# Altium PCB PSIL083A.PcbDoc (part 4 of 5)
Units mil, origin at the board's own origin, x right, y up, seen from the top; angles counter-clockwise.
Board outline 8750 x 2700 mil, 4 copper layers (Top Layer, Signal Layer 1, Signal Layer 2, Bottom Layer), stack 61.2 mil thick; 463 components, 395 nets, 2267 pads, 745 vias.
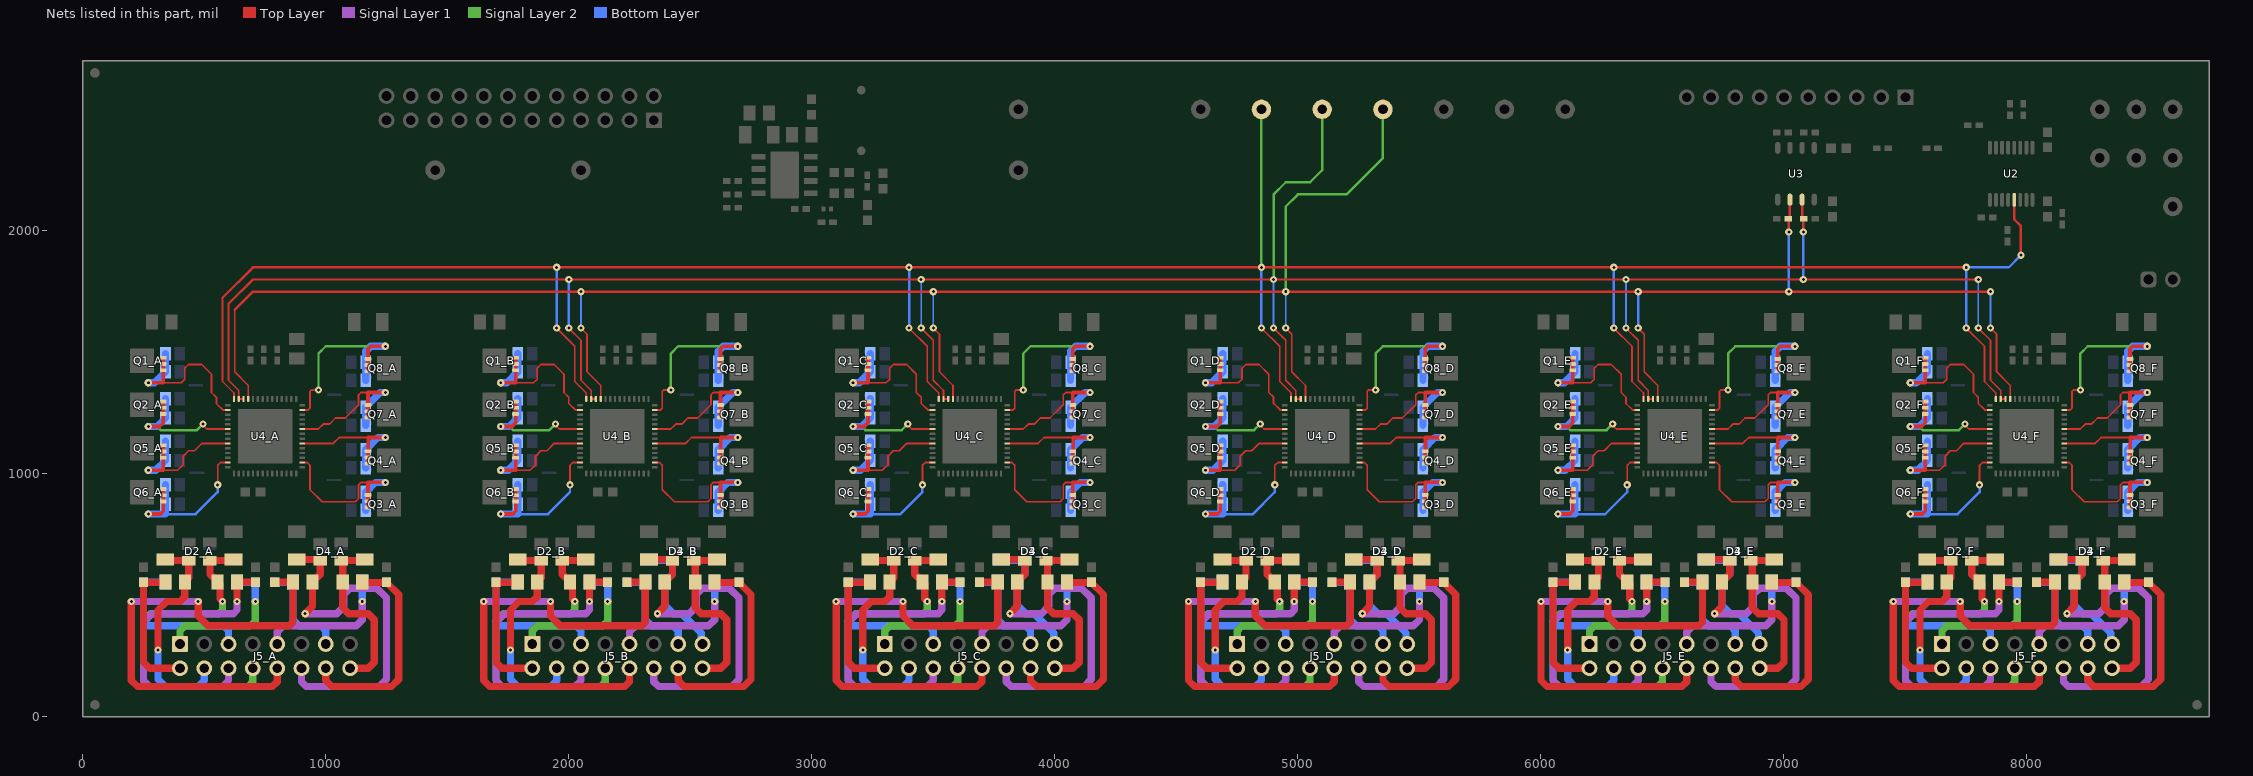
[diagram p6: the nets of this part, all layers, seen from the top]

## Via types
v1: diameter 30, hole 12, Top Layer to Bottom Layer, 610 vias
v2: diameter 19.68, hole 7.87, Top Layer to Bottom Layer, 130 vias
v3: diameter 19.68, hole 7.87, Top Layer to Bottom Layer, tented both sides, 4 vias
v4: diameter 34, hole 16, Top Layer to Bottom Layer, 1 vias

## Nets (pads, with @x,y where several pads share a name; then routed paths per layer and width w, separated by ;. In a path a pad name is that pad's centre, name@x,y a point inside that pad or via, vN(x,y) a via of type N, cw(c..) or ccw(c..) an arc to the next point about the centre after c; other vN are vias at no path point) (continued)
PSE_N4_B: C20_B.2 D3_B.3 F6_B.1 J5_B.15 | length 533.6
  Bottom Layer w30: F6_B.1@2334.41,643.5 D3_B.3@2426.69,643.5 2426.69,586.69 C20_B.2@2395,555 2395,460 2430,425 2465,425 2545,345 2545,305 J5_B.15@2550,300
PSE_N4_C: C20_C.2 D3_C.3 F6_C.1 J5_C.15 | length 533.6
  Bottom Layer w30: F6_C.1@3784.41,643.5 D3_C.3@3876.69,643.5 3876.69,586.69 C20_C.2@3845,555 3845,460 3880,425 3915,425 3995,345 3995,305 J5_C.15@4000,300
PSE_N4_D: C20_D.2 D3_D.3 F6_D.1 J5_D.15 | length 533.6
  Bottom Layer w30: F6_D.1@5234.41,643.5 D3_D.3@5326.69,643.5 5326.69,586.69 C20_D.2@5295,555 5295,460 5330,425 5365,425 5445,345 5445,305 J5_D.15@5450,300
PSE_N4_E: C20_E.2 D3_E.3 F6_E.1 J5_E.15 | length 533.6
  Bottom Layer w30: F6_E.1@6684.41,643.5 D3_E.3@6776.69,643.5 6776.69,586.69 C20_E.2@6745,555 6745,460 6780,425 6815,425 6895,345 6895,305 J5_E.15@6900,300
PSE_N4_F: C20_F.2 D3_F.3 F6_F.1 J5_F.15 | length 533.6
  Bottom Layer w30: F6_F.1@8134.41,643.5 D3_F.3@8226.69,643.5 8226.69,586.69 C20_F.2@8195,555 8195,460 8230,425 8265,425 8345,345 8345,305 J5_F.15@8350,300
PSE_N5_A: C17_A.2 D2_A.2 F3_A.1 J5_A.4 | length 928.3
  Top Layer w30: v1(310,275) 310,440 345,475 400,475 420,495 C17_A.2@420,555 436.69,571.69 D2_A.2@436.69,643.5 F3_A.1@344.41,643.5
  Bottom Layer w30: v1(310,275) 310,155 340,125 475,125 500,150 J5_A.4@500,200
PSE_N5_B: C17_B.2 D2_B.2 F3_B.1 J5_B.4 | length 928.3
  Top Layer w30: v1(1760,275) 1760,440 1795,475 1850,475 1870,495 C17_B.2@1870,555 1886.69,571.69 D2_B.2@1886.69,643.5 F3_B.1@1794.41,643.5
  Bottom Layer w30: v1(1760,275) 1760,155 1790,125 1925,125 1950,150 J5_B.4@1950,200
PSE_N5_C: C17_C.2 D2_C.2 F3_C.1 J5_C.4 | length 928.3
  Top Layer w30: v1(3210,275) 3210,440 3245,475 3300,475 3320,495 C17_C.2@3320,555 3336.69,571.69 D2_C.2@3336.69,643.5 F3_C.1@3244.41,643.5
  Bottom Layer w30: v1(3210,275) 3210,155 3240,125 3375,125 3400,150 J5_C.4@3400,200
PSE_N5_D: C17_D.2 D2_D.2 F3_D.1 J5_D.4 | length 928.3
  Top Layer w30: v1(4660,275) 4660,440 4695,475 4750,475 4770,495 C17_D.2@4770,555 4786.69,571.69 D2_D.2@4786.69,643.5 F3_D.1@4694.41,643.5
  Bottom Layer w30: v1(4660,275) 4660,155 4690,125 4825,125 4850,150 J5_D.4@4850,200
PSE_N5_E: C17_E.2 D2_E.2 F3_E.1 J5_E.4 | length 928.3
  Top Layer w30: v1(6110,275) 6110,440 6145,475 6200,475 6220,495 C17_E.2@6220,555 6236.69,571.69 D2_E.2@6236.69,643.5 F3_E.1@6144.41,643.5
  Bottom Layer w30: v1(6110,275) 6110,155 6140,125 6275,125 6300,150 J5_E.4@6300,200
PSE_N5_F: C17_F.2 D2_F.2 F3_F.1 J5_F.4 | length 928.3
  Top Layer w30: v1(7560,275) 7560,440 7595,475 7650,475 7670,495 C17_F.2@7670,555 7686.69,571.69 D2_F.2@7686.69,643.5 F3_F.1@7594.41,643.5
  Bottom Layer w30: v1(7560,275) 7560,155 7590,125 7725,125 7750,150 J5_F.4@7750,200
PSE_N6_A: C18_A.2 D2_A.3 F4_A.1 J5_A.8 | length 1429.5
  Top Layer w30: v1(575,475) 565,485 565,545 C18_A.2@555,555 523.31,586.69 D2_A.3@523.31,643.5 F4_A.1@615.59,643.5
  Signal Layer 2 w30: v1(575,475) 575,440 560,425 280,425 250,395 250,150 275,125 680,125 700,145 J5_A.8@700,200
PSE_N6_B: C18_B.2 D2_B.3 F4_B.1 J5_B.8 | length 1429.5
  Top Layer w30: v1(2025,475) 2015,485 2015,545 C18_B.2@2005,555 1973.31,586.69 D2_B.3@1973.31,643.5 F4_B.1@2065.59,643.5
  Signal Layer 2 w30: v1(2025,475) 2025,440 2010,425 1730,425 1700,395 1700,150 1725,125 2130,125 2150,145 J5_B.8@2150,200
PSE_N6_C: C18_C.2 D2_C.3 F4_C.1 J5_C.8 | length 1429.5
  Top Layer w30: v1(3475,475) 3465,485 3465,545 C18_C.2@3455,555 3423.31,586.69 D2_C.3@3423.31,643.5 F4_C.1@3515.59,643.5
  Signal Layer 2 w30: v1(3475,475) 3475,440 3460,425 3180,425 3150,395 3150,150 3175,125 3580,125 3600,145 J5_C.8@3600,200
PSE_N6_D: C18_D.2 D2_D.3 F4_D.1 J5_D.8 | length 1429.5
  Top Layer w30: v1(4925,475) 4915,485 4915,545 C18_D.2@4905,555 4873.31,586.69 D2_D.3@4873.31,643.5 F4_D.1@4965.59,643.5
  Signal Layer 2 w30: v1(4925,475) 4925,440 4910,425 4630,425 4600,395 4600,150 4625,125 5030,125 5050,145 J5_D.8@5050,200
PSE_N6_E: C18_E.2 D2_E.3 F4_E.1 J5_E.8 | length 1429.5
  Top Layer w30: v1(6375,475) 6365,485 6365,545 C18_E.2@6355,555 6323.31,586.69 D2_E.3@6323.31,643.5 F4_E.1@6415.59,643.5
  Signal Layer 2 w30: v1(6375,475) 6375,440 6360,425 6080,425 6050,395 6050,150 6075,125 6480,125 6500,145 J5_E.8@6500,200
PSE_N6_F: C18_F.2 D2_F.3 F4_F.1 J5_F.8 | length 1429.5
  Top Layer w30: v1(7825,475) 7815,485 7815,545 C18_F.2@7805,555 7773.31,586.69 D2_F.3@7773.31,643.5 F4_F.1@7865.59,643.5
  Signal Layer 2 w30: v1(7825,475) 7825,440 7810,425 7530,425 7500,395 7500,150 7525,125 7930,125 7950,145 J5_F.8@7950,200
PSE_N7_A: C21_A.2 D4_A.2 F7_A.1 J5_A.12 | length 1521.4
  Top Layer w30: F7_A.1@880,647.91 D4_A.2@972.28,647.91 ; v1(915,425) 945,455 C21_A.2@945,555 976.69,586.69 D4_A.2@976.69,643.5
  Signal Layer 1 w30: J5_A.12@900,200 900,145 920,125 1220,125 1250,155 1250,490 1210,530 1100,530 1075,505 1075,455 1045,425 v1(915,425)
PSE_N7_B: C21_B.2 D4_B.2 F7_B.1 J5_B.12 | length 1521.4
  Top Layer w30: F7_B.1@2330,647.91 D4_B.2@2422.28,647.91 ; v1(2365,425) 2395,455 C21_B.2@2395,555 2426.69,586.69 D4_B.2@2426.69,643.5
  Signal Layer 1 w30: J5_B.12@2350,200 2350,145 2370,125 2670,125 2700,155 2700,490 2660,530 2550,530 2525,505 2525,455 2495,425 v1(2365,425)
PSE_N7_C: C21_C.2 D4_C.2 F7_C.1 J5_C.12 | length 1521.4
  Top Layer w30: F7_C.1@3780,647.91 D4_C.2@3872.28,647.91 ; v1(3815,425) 3845,455 C21_C.2@3845,555 3876.69,586.69 D4_C.2@3876.69,643.5
  Signal Layer 1 w30: J5_C.12@3800,200 3800,145 3820,125 4120,125 4150,155 4150,490 4110,530 4000,530 3975,505 3975,455 3945,425 v1(3815,425)
PSE_N7_D: C21_D.2 D4_D.2 F7_D.1 J5_D.12 | length 1521.4
  Top Layer w30: F7_D.1@5230,647.91 D4_D.2@5322.28,647.91 ; v1(5265,425) 5295,455 C21_D.2@5295,555 5326.69,586.69 D4_D.2@5326.69,643.5
  Signal Layer 1 w30: J5_D.12@5250,200 5250,145 5270,125 5570,125 5600,155 5600,490 5560,530 5450,530 5425,505 5425,455 5395,425 v1(5265,425)
PSE_N7_E: C21_E.2 D4_E.2 F7_E.1 J5_E.12 | length 1521.4
  Top Layer w30: F7_E.1@6680,647.91 D4_E.2@6772.28,647.91 ; v1(6715,425) 6745,455 C21_E.2@6745,555 6776.69,586.69 D4_E.2@6776.69,643.5
  Signal Layer 1 w30: J5_E.12@6700,200 6700,145 6720,125 7020,125 7050,155 7050,490 7010,530 6900,530 6875,505 6875,455 6845,425 v1(6715,425)
PSE_N7_F: C21_F.2 D4_F.2 F7_F.1 J5_F.12 | length 1521.4
  Top Layer w30: F7_F.1@8130,647.91 D4_F.2@8222.28,647.91 ; v1(8165,425) 8195,455 C21_F.2@8195,555 8226.69,586.69 D4_F.2@8226.69,643.5
  Signal Layer 1 w30: J5_F.12@8150,200 8150,145 8170,125 8470,125 8500,155 8500,490 8460,530 8350,530 8325,505 8325,455 8295,425 v1(8165,425)
PSE_N8_A: C22_A.2 D4_A.3 F8_A.1 J5_A.16 | length 715.2
  Top Layer w30: D4_A.3@1063.31,643.5 F8_A.1@1155.59,643.5 ; D4_A.3@1070,636.81 C22_A.2@1070,555 1070,450 1095,425 1175,425 1200,400 1200,225 1175,200 J5_A.16@1100,200
PSE_N8_B: C22_B.2 D4_B.3 F8_B.1 J5_B.16 | length 715.2
  Top Layer w30: D4_B.3@2513.31,643.5 F8_B.1@2605.59,643.5 ; D4_B.3@2520,636.81 C22_B.2@2520,555 2520,450 2545,425 2625,425 2650,400 2650,225 2625,200 J5_B.16@2550,200
PSE_N8_C: C22_C.2 D4_C.3 F8_C.1 J5_C.16 | length 715.2
  Top Layer w30: D4_C.3@3963.31,643.5 F8_C.1@4055.59,643.5 ; D4_C.3@3970,636.81 C22_C.2@3970,555 3970,450 3995,425 4075,425 4100,400 4100,225 4075,200 J5_C.16@4000,200
PSE_N8_D: C22_D.2 D4_D.3 F8_D.1 J5_D.16 | length 715.2
  Top Layer w30: D4_D.3@5413.31,643.5 F8_D.1@5505.59,643.5 ; D4_D.3@5420,636.81 C22_D.2@5420,555 5420,450 5445,425 5525,425 5550,400 5550,225 5525,200 J5_D.16@5450,200
PSE_N8_E: C22_E.2 D4_E.3 F8_E.1 J5_E.16 | length 715.2
  Top Layer w30: D4_E.3@6863.31,643.5 F8_E.1@6955.59,643.5 ; D4_E.3@6870,636.81 C22_E.2@6870,555 6870,450 6895,425 6975,425 7000,400 7000,225 6975,200 J5_E.16@6900,200
PSE_N8_F: C22_F.2 D4_F.3 F8_F.1 J5_F.16 | length 715.2
  Top Layer w30: D4_F.3@8313.31,643.5 F8_F.1@8405.59,643.5 ; D4_F.3@8320,636.81 C22_F.2@8320,555 8320,450 8345,425 8425,425 8450,400 8450,225 8425,200 J5_F.16@8350,200
PSE_OSS_A: TP12.1 U2.13 U4_A.56 U4_B.56 U4_C.56 U4_D.56 U4_E.56 U4_F.56 | length 11757.6
  Top Layer w7: 575,1725 575,1380 622.05,1332.95 U4_A.56@622.05,1308.54 ; v1(1950,1600) 2025,1525 2025,1380 2072.05,1332.95 U4_B.56@2072.05,1308.54 ; v1(3400,1600) 3475,1525 3475,1380 3522.05,1332.95 U4_C.56@3522.05,1308.54 ; v1(4850,1600) 4925,1525 4925,1380 4972.05,1332.95 U4_D.56@4972.05,1308.54 ; v1(6300,1600) 6375,1525 6375,1380 6422.05,1332.95 U4_E.56@6422.05,1308.54 ; v1(7750,1600) 7825,1525 7825,1380 7872.05,1332.95 U4_F.56@7872.05,1308.54
  Top Layer w10: 575,1725 700,1850 v1(1950,1850) v1(3400,1850) v1(4850,1850) v1(6300,1850) v1(7750,1850) ; U2.13@7947.5,2127.72 7947.5,2047.5 7975,2020 v1(7975,1900)
  Signal Layer 2 w10: v1(4850,1850) TP12.1@4850,2500
  Bottom Layer w10: v1(1950,1600) v1(1950,1850) ; v1(3400,1600) v1(3400,1850) ; v1(4850,1600) v1(4850,1850) ; v1(6300,1600) v1(6300,1850) ; v1(7750,1600) v1(7750,1850) 7925,1850 v1(7975,1900)
PSE_P1_A: C15_A.1 J5_A.1 L2_A.2 | length 613.6
  Signal Layer 2 w30: J5_A.1@400,300 400,355 420,375 690,375 710,395 v1(710,475)
  Bottom Layer w30: C15_A.1@636.5,553.5 L2_A.2@710,553.5 v1(710,475)
PSE_P1_B: C15_B.1 J5_B.1 L2_B.2 | length 613.6
  Signal Layer 2 w30: J5_B.1@1850,300 1850,355 1870,375 2140,375 2160,395 v1(2160,475)
  Bottom Layer w30: C15_B.1@2086.5,553.5 L2_B.2@2160,553.5 v1(2160,475)
PSE_P1_C: C15_C.1 J5_C.1 L2_C.2 | length 613.6
  Signal Layer 2 w30: J5_C.1@3300,300 3300,355 3320,375 3590,375 3610,395 v1(3610,475)
  Bottom Layer w30: C15_C.1@3536.5,553.5 L2_C.2@3610,553.5 v1(3610,475)
PSE_P1_D: C15_D.1 J5_D.1 L2_D.2 | length 613.6
  Signal Layer 2 w30: J5_D.1@4750,300 4750,355 4770,375 5040,375 5060,395 v1(5060,475)
  Bottom Layer w30: C15_D.1@4986.5,553.5 L2_D.2@5060,553.5 v1(5060,475)
PSE_P1_E: C15_E.1 J5_E.1 L2_E.2 | length 613.6
  Signal Layer 2 w30: J5_E.1@6200,300 6200,355 6220,375 6490,375 6510,395 v1(6510,475)
  Bottom Layer w30: C15_E.1@6436.5,553.5 L2_E.2@6510,553.5 v1(6510,475)
PSE_P1_F: C15_F.1 J5_F.1 L2_F.2 | length 613.6
  Signal Layer 2 w30: J5_F.1@7650,300 7650,355 7670,375 7940,375 7960,395 v1(7960,475)
  Bottom Layer w30: C15_F.1@7886.5,553.5 L2_F.2@7960,553.5 v1(7960,475)
PSE_P2_A: C16_A.1 J5_A.5 L3_A.2 | length 665.6
  Bottom Layer w30: L3_A.2@250,553.5 250,395 270,375 580,375 600,355 J5_A.5@600,300 ; L3_A.2@254.43,555 C16_A.1@340,555
PSE_P2_B: C16_B.1 J5_B.5 L3_B.2 | length 665.6
  Bottom Layer w30: L3_B.2@1700,553.5 1700,395 1720,375 2030,375 2050,355 J5_B.5@2050,300 ; L3_B.2@1704.43,555 C16_B.1@1790,555
PSE_P2_C: C16_C.1 J5_C.5 L3_C.2 | length 665.6
  Bottom Layer w30: L3_C.2@3150,553.5 3150,395 3170,375 3480,375 3500,355 J5_C.5@3500,300 ; L3_C.2@3154.43,555 C16_C.1@3240,555
PSE_P2_D: C16_D.1 J5_D.5 L3_D.2 | length 665.6
  Bottom Layer w30: L3_D.2@4600,553.5 4600,395 4620,375 4930,375 4950,355 J5_D.5@4950,300 ; L3_D.2@4604.43,555 C16_D.1@4690,555
PSE_P2_E: C16_E.1 J5_E.5 L3_E.2 | length 665.6
  Bottom Layer w30: L3_E.2@6050,553.5 6050,395 6070,375 6380,375 6400,355 J5_E.5@6400,300 ; L3_E.2@6054.43,555 C16_E.1@6140,555
PSE_P2_F: C16_F.1 J5_F.5 L3_F.2 | length 665.6
  Bottom Layer w30: L3_F.2@7500,553.5 7500,395 7520,375 7830,375 7850,355 J5_F.5@7850,300 ; L3_F.2@7504.43,555 C16_F.1@7590,555
PSE_P3_A: C19_A.1 J5_A.9 L6_A.2 | length 671.2
  Signal Layer 1 w30: J5_A.9@800,300 800,350 825,375 1125,375 1150,400 v1(1150,475)
  Bottom Layer w30: v1(1150,475) C19_A.1@1150,552.01 ; C19_A.1@1151.5,553.5 L6_A.2@1250,553.5
PSE_P3_B: C19_B.1 J5_B.9 L6_B.2 | length 671.2
  Signal Layer 1 w30: J5_B.9@2250,300 2250,350 2275,375 2575,375 2600,400 v1(2600,475)
  Bottom Layer w30: v1(2600,475) C19_B.1@2600,552.01 ; C19_B.1@2601.5,553.5 L6_B.2@2700,553.5
PSE_P3_C: C19_C.1 J5_C.9 L6_C.2 | length 671.2
  Signal Layer 1 w30: J5_C.9@3700,300 3700,350 3725,375 4025,375 4050,400 v1(4050,475)
  Bottom Layer w30: v1(4050,475) C19_C.1@4050,552.01 ; C19_C.1@4051.5,553.5 L6_C.2@4150,553.5
PSE_P3_D: C19_D.1 J5_D.9 L6_D.2 | length 671.2
  Signal Layer 1 w30: J5_D.9@5150,300 5150,350 5175,375 5475,375 5500,400 v1(5500,475)
  Bottom Layer w30: v1(5500,475) C19_D.1@5500,552.01 ; C19_D.1@5501.5,553.5 L6_D.2@5600,553.5
PSE_P3_E: C19_E.1 J5_E.9 L6_E.2 | length 671.2
  Signal Layer 1 w30: J5_E.9@6600,300 6600,350 6625,375 6925,375 6950,400 v1(6950,475)
  Bottom Layer w30: v1(6950,475) C19_E.1@6950,552.01 ; C19_E.1@6951.5,553.5 L6_E.2@7050,553.5
PSE_P3_F: C19_F.1 J5_F.9 L6_F.2 | length 671.2
  Signal Layer 1 w30: J5_F.9@8050,300 8050,350 8075,375 8375,375 8400,400 v1(8400,475)
  Bottom Layer w30: v1(8400,475) C19_F.1@8400,552.01 ; C19_F.1@8401.5,553.5 L6_F.2@8500,553.5
PSE_P4_A: C20_A.1 J5_A.13 L7_A.2 | length 437.1
  Bottom Layer w30: L7_A.2@790,553.5 C20_A.1@863.5,553.5 ; C20_A.1@865,555 865,400 890,375 980,375 1000,355 J5_A.13@1000,300
PSE_P4_B: C20_B.1 J5_B.13 L7_B.2 | length 437.1
  Bottom Layer w30: L7_B.2@2240,553.5 C20_B.1@2313.5,553.5 ; C20_B.1@2315,555 2315,400 2340,375 2430,375 2450,355 J5_B.13@2450,300
PSE_P4_C: C20_C.1 J5_C.13 L7_C.2 | length 437.1
  Bottom Layer w30: L7_C.2@3690,553.5 C20_C.1@3763.5,553.5 ; C20_C.1@3765,555 3765,400 3790,375 3880,375 3900,355 J5_C.13@3900,300
PSE_P4_D: C20_D.1 J5_D.13 L7_D.2 | length 437.1
  Bottom Layer w30: L7_D.2@5140,553.5 C20_D.1@5213.5,553.5 ; C20_D.1@5215,555 5215,400 5240,375 5330,375 5350,355 J5_D.13@5350,300
PSE_P4_E: C20_E.1 J5_E.13 L7_E.2 | length 437.1
  Bottom Layer w30: L7_E.2@6590,553.5 C20_E.1@6663.5,553.5 ; C20_E.1@6665,555 6665,400 6690,375 6780,375 6800,355 J5_E.13@6800,300
PSE_P4_F: C20_F.1 J5_F.13 L7_F.2 | length 437.1
  Bottom Layer w30: L7_F.2@8040,553.5 C20_F.1@8113.5,553.5 ; C20_F.1@8115,555 8115,400 8140,375 8230,375 8250,355 J5_F.13@8250,300
PSE_P5_A: C17_A.1 J5_A.2 L4_A.2 | length 577.4
  Top Layer w30: C17_A.1@338.5,553.5 L4_A.2@250,553.5 250,225 275,200 J5_A.2@400,200
PSE_P5_B: C17_B.1 J5_B.2 L4_B.2 | length 577.4
  Top Layer w30: C17_B.1@1788.5,553.5 L4_B.2@1700,553.5 1700,225 1725,200 J5_B.2@1850,200
PSE_P5_C: C17_C.1 J5_C.2 L4_C.2 | length 577.4
  Top Layer w30: C17_C.1@3238.5,553.5 L4_C.2@3150,553.5 3150,225 3175,200 J5_C.2@3300,200
PSE_P5_D: C17_D.1 J5_D.2 L4_D.2 | length 577.4
  Top Layer w30: C17_D.1@4688.5,553.5 L4_D.2@4600,553.5 4600,225 4625,200 J5_D.2@4750,200
PSE_P5_E: C17_E.1 J5_E.2 L4_E.2 | length 577.4
  Top Layer w30: C17_E.1@6138.5,553.5 L4_E.2@6050,553.5 6050,225 6075,200 J5_E.2@6200,200
PSE_P5_F: C17_F.1 J5_F.2 L4_F.2 | length 577.4
  Top Layer w30: C17_F.1@7588.5,553.5 L4_F.2@7500,553.5 7500,225 7525,200 J5_F.2@7650,200
PSE_P6_A: C18_A.1 J5_A.6 L5_A.2 | length 1254.9
  Top Layer w30: v1(635,475) C18_A.1@635,555 L5_A.2@708.5,555
  Signal Layer 1 w30: J5_A.6@600,200 600,150 575,125 275,125 250,150 250,390 285,425 620,425 635,440 v1(635,475)
PSE_P6_B: C18_B.1 J5_B.6 L5_B.2 | length 1254.9
  Top Layer w30: v1(2085,475) C18_B.1@2085,555 L5_B.2@2158.5,555
  Signal Layer 1 w30: J5_B.6@2050,200 2050,150 2025,125 1725,125 1700,150 1700,390 1735,425 2070,425 2085,440 v1(2085,475)
PSE_P6_C: C18_C.1 J5_C.6 L5_C.2 | length 1254.9
  Top Layer w30: v1(3535,475) C18_C.1@3535,555 L5_C.2@3608.5,555
  Signal Layer 1 w30: J5_C.6@3500,200 3500,150 3475,125 3175,125 3150,150 3150,390 3185,425 3520,425 3535,440 v1(3535,475)
PSE_P6_D: C18_D.1 J5_D.6 L5_D.2 | length 1254.9
  Top Layer w30: v1(4985,475) C18_D.1@4985,555 L5_D.2@5058.5,555
  Signal Layer 1 w30: J5_D.6@4950,200 4950,150 4925,125 4625,125 4600,150 4600,390 4635,425 4970,425 4985,440 v1(4985,475)
PSE_P6_E: C18_E.1 J5_E.6 L5_E.2 | length 1254.9
  Top Layer w30: v1(6435,475) C18_E.1@6435,555 L5_E.2@6508.5,555
  Signal Layer 1 w30: J5_E.6@6400,200 6400,150 6375,125 6075,125 6050,150 6050,390 6085,425 6420,425 6435,440 v1(6435,475)
PSE_P6_F: C18_F.1 J5_F.6 L5_F.2 | length 1254.9
  Top Layer w30: v1(7885,475) C18_F.1@7885,555 L5_F.2@7958.5,555
  Signal Layer 1 w30: J5_F.6@7850,200 7850,150 7825,125 7525,125 7500,150 7500,390 7535,425 7870,425 7885,440 v1(7885,475)
PSE_P7_A: C21_A.1 J5_A.10 L8_A.2 | length 1984.9
  Top Layer w30: v1(200,475) 200,150 225,125 780,125 800,145 J5_A.10@800,200 ; v1(475,475) 475,415 515,375 850,375 865,390 C21_A.1@865,555 L8_A.2@791.5,555
  Signal Layer 1 w30: v1(200,475) v1(475,475)
PSE_P7_B: C21_B.1 J5_B.10 L8_B.2 | length 1984.9
  Top Layer w30: v1(1650,475) 1650,150 1675,125 2230,125 2250,145 J5_B.10@2250,200 ; v1(1925,475) 1925,415 1965,375 2300,375 2315,390 C21_B.1@2315,555 L8_B.2@2241.5,555
  Signal Layer 1 w30: v1(1650,475) v1(1925,475)
PSE_P7_C: C21_C.1 J5_C.10 L8_C.2 | length 1984.9
  Top Layer w30: v1(3100,475) 3100,150 3125,125 3680,125 3700,145 J5_C.10@3700,200 ; v1(3375,475) 3375,415 3415,375 3750,375 3765,390 C21_C.1@3765,555 L8_C.2@3691.5,555
  Signal Layer 1 w30: v1(3100,475) v1(3375,475)
PSE_P7_D: C21_D.1 J5_D.10 L8_D.2 | length 1984.9
  Top Layer w30: v1(4550,475) 4550,150 4575,125 5130,125 5150,145 J5_D.10@5150,200 ; v1(4825,475) 4825,415 4865,375 5200,375 5215,390 C21_D.1@5215,555 L8_D.2@5141.5,555
  Signal Layer 1 w30: v1(4550,475) v1(4825,475)
PSE_P7_E: C21_E.1 J5_E.10 L8_E.2 | length 1984.9
  Top Layer w30: v1(6000,475) 6000,150 6025,125 6580,125 6600,145 J5_E.10@6600,200 ; v1(6275,475) 6275,415 6315,375 6650,375 6665,390 C21_E.1@6665,555 L8_E.2@6591.5,555
  Signal Layer 1 w30: v1(6000,475) v1(6275,475)
PSE_P7_F: C21_F.1 J5_F.10 L8_F.2 | length 1984.9
  Top Layer w30: v1(7450,475) 7450,150 7475,125 8030,125 8050,145 J5_F.10@8050,200 ; v1(7725,475) 7725,415 7765,375 8100,375 8115,390 C21_F.1@8115,555 L8_F.2@8041.5,555
  Signal Layer 1 w30: v1(7450,475) v1(7725,475)
PSE_P8_A: C22_A.1 J5_A.14 L9_A.2 | length 890.5
  Top Layer w30: J5_A.14@1000,200 1000,150 1025,125 1270,125 1300,155 1300,503.5 L9_A.2@1250,553.5 C22_A.1@1151.5,553.5
PSE_P8_B: C22_B.1 J5_B.14 L9_B.2 | length 890.5
  Top Layer w30: J5_B.14@2450,200 2450,150 2475,125 2720,125 2750,155 2750,503.5 L9_B.2@2700,553.5 C22_B.1@2601.5,553.5
PSE_P8_C: C22_C.1 J5_C.14 L9_C.2 | length 890.5
  Top Layer w30: J5_C.14@3900,200 3900,150 3925,125 4170,125 4200,155 4200,503.5 L9_C.2@4150,553.5 C22_C.1@4051.5,553.5
PSE_P8_D: C22_D.1 J5_D.14 L9_D.2 | length 890.5
  Top Layer w30: J5_D.14@5350,200 5350,150 5375,125 5620,125 5650,155 5650,503.5 L9_D.2@5600,553.5 C22_D.1@5501.5,553.5
PSE_P8_E: C22_E.1 J5_E.14 L9_E.2 | length 890.5
  Top Layer w30: J5_E.14@6800,200 6800,150 6825,125 7070,125 7100,155 7100,503.5 L9_E.2@7050,553.5 C22_E.1@6951.5,553.5
PSE_P8_F: C22_F.1 J5_F.14 L9_F.2 | length 890.5
  Top Layer w30: J5_F.14@8250,200 8250,150 8275,125 8520,125 8550,155 8550,503.5 L9_F.2@8500,553.5 C22_F.1@8401.5,553.5
PSE_S1_A: Q1_A.1 Q1_A.2 Q1_A.3 R15_A.1 R16_A.1 U4_A.2 | length 787.1
  Top Layer w7: 330,1375 405,1375 420,1390 420,1435 435,1450 490,1450 530,1410 530,1335 550,1315 550,1290 576.73,1263.27 U4_A.2@596.46,1263.27
  Top Layer w15: v1(270,1375) 330,1375 331.02,1376.02 Q1_A.1@331.02,1426.61 Q1_A.2@331.02,1452.21 Q1_A.3@331.02,1477.8
  Bottom Layer w30: v1(270,1375) 295.47,1375 R16_A.1@340.47,1420 R15_A.1@340.47,1495
PSE_S1_B: Q1_B.1 Q1_B.2 Q1_B.3 R15_B.1 R16_B.1 U4_B.2 | length 787.1
  Top Layer w7: 1780,1375 1855,1375 1870,1390 1870,1435 1885,1450 1940,1450 1980,1410 1980,1335 2000,1315 2000,1290 2026.73,1263.27 U4_B.2@2046.46,1263.27
  Top Layer w15: v1(1720,1375) 1780,1375 1781.02,1376.02 Q1_B.1@1781.02,1426.61 Q1_B.2@1781.02,1452.21 Q1_B.3@1781.02,1477.8
  Bottom Layer w30: v1(1720,1375) 1745.47,1375 R16_B.1@1790.47,1420 R15_B.1@1790.47,1495
PSE_S1_C: Q1_C.1 Q1_C.2 Q1_C.3 R15_C.1 R16_C.1 U4_C.2 | length 787.1
  Top Layer w7: 3230,1375 3305,1375 3320,1390 3320,1435 3335,1450 3390,1450 3430,1410 3430,1335 3450,1315 3450,1290 3476.73,1263.27 U4_C.2@3496.46,1263.27
  Top Layer w15: v1(3170,1375) 3230,1375 3231.02,1376.02 Q1_C.1@3231.02,1426.61 Q1_C.2@3231.02,1452.21 Q1_C.3@3231.02,1477.8
  Bottom Layer w30: v1(3170,1375) 3195.47,1375 R16_C.1@3240.47,1420 R15_C.1@3240.47,1495
PSE_S1_D: Q1_D.1 Q1_D.2 Q1_D.3 R15_D.1 R16_D.1 U4_D.2 | length 787.1
  Top Layer w7: 4680,1375 4755,1375 4770,1390 4770,1435 4785,1450 4840,1450 4880,1410 4880,1335 4900,1315 4900,1290 4926.73,1263.27 U4_D.2@4946.46,1263.27
  Top Layer w15: v1(4620,1375) 4680,1375 4681.02,1376.02 Q1_D.1@4681.02,1426.61 Q1_D.2@4681.02,1452.21 Q1_D.3@4681.02,1477.8
  Bottom Layer w30: v1(4620,1375) 4645.47,1375 R16_D.1@4690.47,1420 R15_D.1@4690.47,1495
PSE_S1_E: Q1_E.1 Q1_E.2 Q1_E.3 R15_E.1 R16_E.1 U4_E.2 | length 787.1
  Top Layer w7: 6130,1375 6205,1375 6220,1390 6220,1435 6235,1450 6290,1450 6330,1410 6330,1335 6350,1315 6350,1290 6376.73,1263.27 U4_E.2@6396.46,1263.27
  Top Layer w15: v1(6070,1375) 6130,1375 6131.02,1376.02 Q1_E.1@6131.02,1426.61 Q1_E.2@6131.02,1452.21 Q1_E.3@6131.02,1477.8
  Bottom Layer w30: v1(6070,1375) 6095.47,1375 R16_E.1@6140.47,1420 R15_E.1@6140.47,1495
PSE_S1_F: Q1_F.1 Q1_F.2 Q1_F.3 R15_F.1 R16_F.1 U4_F.2 | length 787.1
  Top Layer w7: 7580,1375 7655,1375 7670,1390 7670,1435 7685,1450 7740,1450 7780,1410 7780,1335 7800,1315 7800,1290 7826.73,1263.27 U4_F.2@7846.46,1263.27
  Top Layer w15: v1(7520,1375) 7580,1375 7581.02,1376.02 Q1_F.1@7581.02,1426.61 Q1_F.2@7581.02,1452.21 Q1_F.3@7581.02,1477.8
  Bottom Layer w30: v1(7520,1375) 7545.47,1375 R16_F.1@7590.47,1420 R15_F.1@7590.47,1495
PSE_S2_A: Q2_A.1 Q2_A.2 Q2_A.3 R17_A.1 R18_A.1 U4_A.6 | length 675.9
  Top Layer w7: v1@490,1205 510.47,1184.53 U4_A.6@596.46,1184.53
  Top Layer w15: v1(270,1195) 315,1195 331.02,1211.02 Q2_A.1@331.02,1246.61 Q2_A.2@331.02,1272.21 Q2_A.3@331.02,1297.8
  Signal Layer 2 w10: v1(270,1195) 305.47,1195 320.47,1180 470,1180 v1(495,1205)
  Bottom Layer w30: v1(270,1195) 305.47,1195 R18_A.1@340.47,1230 R17_A.1@340.47,1310
PSE_S2_B: Q2_B.1 Q2_B.2 Q2_B.3 R17_B.1 R18_B.1 U4_B.6 | length 675.9
  Top Layer w7: v1@1940,1205 1960.47,1184.53 U4_B.6@2046.46,1184.53
  Top Layer w15: v1(1720,1195) 1765,1195 1781.02,1211.02 Q2_B.1@1781.02,1246.61 Q2_B.2@1781.02,1272.21 Q2_B.3@1781.02,1297.8
  Signal Layer 2 w10: v1(1720,1195) 1755.47,1195 1770.47,1180 1920,1180 v1(1945,1205)
  Bottom Layer w30: v1(1720,1195) 1755.47,1195 R18_B.1@1790.47,1230 R17_B.1@1790.47,1310
PSE_S2_C: Q2_C.1 Q2_C.2 Q2_C.3 R17_C.1 R18_C.1 U4_C.6 | length 675.9
  Top Layer w7: v1@3390,1205 3410.47,1184.53 U4_C.6@3496.46,1184.53
  Top Layer w15: v1(3170,1195) 3215,1195 3231.02,1211.02 Q2_C.1@3231.02,1246.61 Q2_C.2@3231.02,1272.21 Q2_C.3@3231.02,1297.8
  Signal Layer 2 w10: v1(3170,1195) 3205.47,1195 3220.47,1180 3370,1180 v1(3395,1205)
  Bottom Layer w30: v1(3170,1195) 3205.47,1195 R18_C.1@3240.47,1230 R17_C.1@3240.47,1310
PSE_S2_D: Q2_D.1 Q2_D.2 Q2_D.3 R17_D.1 R18_D.1 U4_D.6 | length 675.9
  Top Layer w7: v1@4840,1205 4860.47,1184.53 U4_D.6@4946.46,1184.53
  Top Layer w15: v1(4620,1195) 4665,1195 4681.02,1211.02 Q2_D.1@4681.02,1246.61 Q2_D.2@4681.02,1272.21 Q2_D.3@4681.02,1297.8
  Signal Layer 2 w10: v1(4620,1195) 4655.47,1195 4670.47,1180 4820,1180 v1(4845,1205)
  Bottom Layer w30: v1(4620,1195) 4655.47,1195 R18_D.1@4690.47,1230 R17_D.1@4690.47,1310
PSE_S2_E: Q2_E.1 Q2_E.2 Q2_E.3 R17_E.1 R18_E.1 U4_E.6 | length 675.9
  Top Layer w7: v1@6290,1205 6310.47,1184.53 U4_E.6@6396.46,1184.53
  Top Layer w15: v1(6070,1195) 6115,1195 6131.02,1211.02 Q2_E.1@6131.02,1246.61 Q2_E.2@6131.02,1272.21 Q2_E.3@6131.02,1297.8
  Signal Layer 2 w10: v1(6070,1195) 6105.47,1195 6120.47,1180 6270,1180 v1(6295,1205)
  Bottom Layer w30: v1(6070,1195) 6105.47,1195 R18_E.1@6140.47,1230 R17_E.1@6140.47,1310
PSE_S2_F: Q2_F.1 Q2_F.2 Q2_F.3 R17_F.1 R18_F.1 U4_F.6 | length 675.9
  Top Layer w7: v1@7740,1205 7760.47,1184.53 U4_F.6@7846.46,1184.53
  Top Layer w15: v1(7520,1195) 7565,1195 7581.02,1211.02 Q2_F.1@7581.02,1246.61 Q2_F.2@7581.02,1272.21 Q2_F.3@7581.02,1297.8
  Signal Layer 2 w10: v1(7520,1195) 7555.47,1195 7570.47,1180 7720,1180 v1(7745,1205)
  Bottom Layer w30: v1(7520,1195) 7555.47,1195 R18_F.1@7590.47,1230 R17_F.1@7590.47,1310
PSE_S3_A: Q5_A.1 Q5_A.2 Q5_A.3 R23_A.1 R24_A.1 U4_A.9 | length 662.6
  Top Layer w7: 331.02,1015 390,1015 413.31,1038.31 413.31,1073.31 435,1095 460,1095 490.47,1125.47 U4_A.9@596.46,1125.47
  Top Layer w15: v1(270,1015) 331.02,1015 Q5_A.1@331.02,1066.61 Q5_A.2@331.02,1092.21 Q5_A.3@331.02,1117.8
  Bottom Layer w30: v1(270,1015) 300.47,1015 R24_A.1@340.47,1055 R23_A.1@340.47,1135
PSE_S3_B: Q5_B.1 Q5_B.2 Q5_B.3 R23_B.1 R24_B.1 U4_B.9 | length 662.6
  Top Layer w7: 1781.02,1015 1840,1015 1863.31,1038.31 1863.31,1073.31 1885,1095 1910,1095 1940.47,1125.47 U4_B.9@2046.46,1125.47
  Top Layer w15: v1(1720,1015) 1781.02,1015 Q5_B.1@1781.02,1066.61 Q5_B.2@1781.02,1092.21 Q5_B.3@1781.02,1117.8
  Bottom Layer w30: v1(1720,1015) 1750.47,1015 R24_B.1@1790.47,1055 R23_B.1@1790.47,1135
PSE_S3_C: Q5_C.1 Q5_C.2 Q5_C.3 R23_C.1 R24_C.1 U4_C.9 | length 662.6
  Top Layer w7: 3231.02,1015 3290,1015 3313.31,1038.31 3313.31,1073.31 3335,1095 3360,1095 3390.47,1125.47 U4_C.9@3496.46,1125.47
  Top Layer w15: v1(3170,1015) 3231.02,1015 Q5_C.1@3231.02,1066.61 Q5_C.2@3231.02,1092.21 Q5_C.3@3231.02,1117.8
  Bottom Layer w30: v1(3170,1015) 3200.47,1015 R24_C.1@3240.47,1055 R23_C.1@3240.47,1135
PSE_S3_D: Q5_D.1 Q5_D.2 Q5_D.3 R23_D.1 R24_D.1 U4_D.9 | length 662.6
  Top Layer w7: 4681.02,1015 4740,1015 4763.31,1038.31 4763.31,1073.31 4785,1095 4810,1095 4840.47,1125.47 U4_D.9@4946.46,1125.47
  Top Layer w15: v1(4620,1015) 4681.02,1015 Q5_D.1@4681.02,1066.61 Q5_D.2@4681.02,1092.21 Q5_D.3@4681.02,1117.8
  Bottom Layer w30: v1(4620,1015) 4650.47,1015 R24_D.1@4690.47,1055 R23_D.1@4690.47,1135
PSE_S3_E: Q5_E.1 Q5_E.2 Q5_E.3 R23_E.1 R24_E.1 U4_E.9 | length 662.6
  Top Layer w7: 6131.02,1015 6190,1015 6213.31,1038.31 6213.31,1073.31 6235,1095 6260,1095 6290.47,1125.47 U4_E.9@6396.46,1125.47
  Top Layer w15: v1(6070,1015) 6131.02,1015 Q5_E.1@6131.02,1066.61 Q5_E.2@6131.02,1092.21 Q5_E.3@6131.02,1117.8
  Bottom Layer w30: v1(6070,1015) 6100.47,1015 R24_E.1@6140.47,1055 R23_E.1@6140.47,1135
PSE_S3_F: Q5_F.1 Q5_F.2 Q5_F.3 R23_F.1 R24_F.1 U4_F.9 | length 662.6
  Top Layer w7: 7581.02,1015 7640,1015 7663.31,1038.31 7663.31,1073.31 7685,1095 7710,1095 7740.47,1125.47 U4_F.9@7846.46,1125.47
  Top Layer w15: v1(7520,1015) 7581.02,1015 Q5_F.1@7581.02,1066.61 Q5_F.2@7581.02,1092.21 Q5_F.3@7581.02,1117.8
  Bottom Layer w30: v1(7520,1015) 7550.47,1015 R24_F.1@7590.47,1055 R23_F.1@7590.47,1135
PSE_S4_A: Q6_A.1 Q6_A.2 Q6_A.3 R25_A.1 R26_A.1 U4_A.13 | length 755.7
  Top Layer w7: v1(555,955) 555,1035 566.73,1046.73 U4_A.13@596.46,1046.73
  Top Layer w15: v1(270,835) 320,835 331.02,846.02 Q6_A.1@331.02,886.61 Q6_A.2@331.02,912.21 Q6_A.3@331.02,937.8
  Bottom Layer w10: 340.91,834.57 464.57,834.57 555,925 v1(555,955)
  Bottom Layer w30: v1(270,835) 340.47,835 R26_A.1@340.47,875 R25_A.1@340.47,955
PSE_S4_B: Q6_B.1 Q6_B.2 Q6_B.3 R25_B.1 R26_B.1 U4_B.13 | length 755.7
  Top Layer w7: v1(2005,955) 2005,1035 2016.73,1046.73 U4_B.13@2046.46,1046.73
  Top Layer w15: v1(1720,835) 1770,835 1781.02,846.02 Q6_B.1@1781.02,886.61 Q6_B.2@1781.02,912.21 Q6_B.3@1781.02,937.8
  Bottom Layer w10: 1790.91,834.57 1914.57,834.57 2005,925 v1(2005,955)
  Bottom Layer w30: v1(1720,835) 1790.47,835 R26_B.1@1790.47,875 R25_B.1@1790.47,955
PSE_S4_C: Q6_C.1 Q6_C.2 Q6_C.3 R25_C.1 R26_C.1 U4_C.13 | length 755.7
  Top Layer w7: v1(3455,955) 3455,1035 3466.73,1046.73 U4_C.13@3496.46,1046.73
  Top Layer w15: v1(3170,835) 3220,835 3231.02,846.02 Q6_C.1@3231.02,886.61 Q6_C.2@3231.02,912.21 Q6_C.3@3231.02,937.8
  Bottom Layer w10: 3240.91,834.57 3364.57,834.57 3455,925 v1(3455,955)
  Bottom Layer w30: v1(3170,835) 3240.47,835 R26_C.1@3240.47,875 R25_C.1@3240.47,955
PSE_S4_D: Q6_D.1 Q6_D.2 Q6_D.3 R25_D.1 R26_D.1 U4_D.13 | length 755.7
  Top Layer w7: v1(4905,955) 4905,1035 4916.73,1046.73 U4_D.13@4946.46,1046.73
  Top Layer w15: v1(4620,835) 4670,835 4681.02,846.02 Q6_D.1@4681.02,886.61 Q6_D.2@4681.02,912.21 Q6_D.3@4681.02,937.8
  Bottom Layer w10: 4690.91,834.57 4814.57,834.57 4905,925 v1(4905,955)
  Bottom Layer w30: v1(4620,835) 4690.47,835 R26_D.1@4690.47,875 R25_D.1@4690.47,955
PSE_S4_E: Q6_E.1 Q6_E.2 Q6_E.3 R25_E.1 R26_E.1 U4_E.13 | length 755.7
  Top Layer w7: v1(6355,955) 6355,1035 6366.73,1046.73 U4_E.13@6396.46,1046.73
  Top Layer w15: v1(6070,835) 6120,835 6131.02,846.02 Q6_E.1@6131.02,886.61 Q6_E.2@6131.02,912.21 Q6_E.3@6131.02,937.8
  Bottom Layer w10: 6140.91,834.57 6264.57,834.57 6355,925 v1(6355,955)
  Bottom Layer w30: v1(6070,835) 6140.47,835 R26_E.1@6140.47,875 R25_E.1@6140.47,955
PSE_S4_F: Q6_F.1 Q6_F.2 Q6_F.3 R25_F.1 R26_F.1 U4_F.13 | length 755.7
  Top Layer w7: v1(7805,955) 7805,1035 7816.73,1046.73 U4_F.13@7846.46,1046.73
  Top Layer w15: v1(7520,835) 7570,835 7581.02,846.02 Q6_F.1@7581.02,886.61 Q6_F.2@7581.02,912.21 Q6_F.3@7581.02,937.8
  Bottom Layer w10: 7590.91,834.57 7714.57,834.57 7805,925 v1(7805,955)
  Bottom Layer w30: v1(7520,835) 7590.47,835 R26_F.1@7590.47,875 R25_F.1@7590.47,955
PSE_S5_A: Q3_A.1 Q3_A.2 Q3_A.3 R19_A.1 R20_A.1 U4_A.30 | length 809.1
  Top Layer w7: U4_A.30@903.54,1046.73 923.27,1046.73 935,1035 935,935 985,885 1121.5,885 1135,898.5 1135,955 1145,965 1175,965
  Top Layer w15: Q3_A.3@1173.98,862.21 Q3_A.2@1173.98,887.8 Q3_A.1@1173.98,913.39 1173.98,965 v1(1245,965)
  Bottom Layer w30: R19_A.1@1164.53,850 R20_A.1@1164.53,925 1204.53,965 v1(1245,965)
PSE_S5_B: Q3_B.1 Q3_B.2 Q3_B.3 R19_B.1 R20_B.1 U4_B.30 | length 809.1
  Top Layer w7: U4_B.30@2353.54,1046.73 2373.27,1046.73 2385,1035 2385,935 2435,885 2571.5,885 2585,898.5 2585,955 2595,965 2625,965
  Top Layer w15: Q3_B.3@2623.98,862.21 Q3_B.2@2623.98,887.8 Q3_B.1@2623.98,913.39 2623.98,965 v1(2695,965)
  Bottom Layer w30: R19_B.1@2614.53,850 R20_B.1@2614.53,925 2654.53,965 v1(2695,965)
PSE_S5_C: Q3_C.1 Q3_C.2 Q3_C.3 R19_C.1 R20_C.1 U4_C.30 | length 809.1
  Top Layer w7: U4_C.30@3803.54,1046.73 3823.27,1046.73 3835,1035 3835,935 3885,885 4021.5,885 4035,898.5 4035,955 4045,965 4075,965
  Top Layer w15: Q3_C.3@4073.98,862.21 Q3_C.2@4073.98,887.8 Q3_C.1@4073.98,913.39 4073.98,965 v1(4145,965)
  Bottom Layer w30: R19_C.1@4064.53,850 R20_C.1@4064.53,925 4104.53,965 v1(4145,965)
PSE_S5_D: Q3_D.1 Q3_D.2 Q3_D.3 R19_D.1 R20_D.1 U4_D.30 | length 809.1
  Top Layer w7: U4_D.30@5253.54,1046.73 5273.27,1046.73 5285,1035 5285,935 5335,885 5471.5,885 5485,898.5 5485,955 5495,965 5525,965
  Top Layer w15: Q3_D.3@5523.98,862.21 Q3_D.2@5523.98,887.8 Q3_D.1@5523.98,913.39 5523.98,965 v1(5595,965)
  Bottom Layer w30: R19_D.1@5514.53,850 R20_D.1@5514.53,925 5554.53,965 v1(5595,965)
PSE_S5_E: Q3_E.1 Q3_E.2 Q3_E.3 R19_E.1 R20_E.1 U4_E.30 | length 809.1
  Top Layer w7: U4_E.30@6703.54,1046.73 6723.27,1046.73 6735,1035 6735,935 6785,885 6921.5,885 6935,898.5 6935,955 6945,965 6975,965
  Top Layer w15: Q3_E.3@6973.98,862.21 Q3_E.2@6973.98,887.8 Q3_E.1@6973.98,913.39 6973.98,965 v1(7045,965)
  Bottom Layer w30: R19_E.1@6964.53,850 R20_E.1@6964.53,925 7004.53,965 v1(7045,965)
PSE_S5_F: Q3_F.1 Q3_F.2 Q3_F.3 R19_F.1 R20_F.1 U4_F.30 | length 809.1
  Top Layer w7: U4_F.30@8153.54,1046.73 8173.27,1046.73 8185,1035 8185,935 8235,885 8371.5,885 8385,898.5 8385,955 8395,965 8425,965
  Top Layer w15: Q3_F.3@8423.98,862.21 Q3_F.2@8423.98,887.8 Q3_F.1@8423.98,913.39 8423.98,965 v1(8495,965)
  Bottom Layer w30: R19_F.1@8414.53,850 R20_F.1@8414.53,925 8454.53,965 v1(8495,965)
PSE_S6_A: Q4_A.1 Q4_A.2 Q4_A.3 R21_A.1 R22_A.1 U4_A.34 | length 634.6
  Top Layer w7: U4_A.34@903.54,1125.47 1030.47,1125.47 1055,1150 1175,1150
  Top Layer w15: Q4_A.3@1173.98,1042.21 Q4_A.2@1173.98,1067.8 Q4_A.1@1173.98,1093.39 ; Q4_A.1@1175,1094.41 1175,1150 v1(1245,1150)
  Bottom Layer w30: R21_A.1@1164.53,1025 R22_A.1@1164.53,1100 1214.53,1150 v1(1245,1150)
PSE_S6_B: Q4_B.1 Q4_B.2 Q4_B.3 R21_B.1 R22_B.1 U4_B.34 | length 634.6
  Top Layer w7: U4_B.34@2353.54,1125.47 2480.47,1125.47 2505,1150 2625,1150
  Top Layer w15: Q4_B.3@2623.98,1042.21 Q4_B.2@2623.98,1067.8 Q4_B.1@2623.98,1093.39 ; Q4_B.1@2625,1094.41 2625,1150 v1(2695,1150)
  Bottom Layer w30: R21_B.1@2614.53,1025 R22_B.1@2614.53,1100 2664.53,1150 v1(2695,1150)
PSE_S6_C: Q4_C.1 Q4_C.2 Q4_C.3 R21_C.1 R22_C.1 U4_C.34 | length 634.6
  Top Layer w7: U4_C.34@3803.54,1125.47 3930.47,1125.47 3955,1150 4075,1150
  Top Layer w15: Q4_C.3@4073.98,1042.21 Q4_C.2@4073.98,1067.8 Q4_C.1@4073.98,1093.39 ; Q4_C.1@4075,1094.41 4075,1150 v1(4145,1150)
  Bottom Layer w30: R21_C.1@4064.53,1025 R22_C.1@4064.53,1100 4114.53,1150 v1(4145,1150)
PSE_S6_D: Q4_D.1 Q4_D.2 Q4_D.3 R21_D.1 R22_D.1 U4_D.34 | length 634.6
  Top Layer w7: U4_D.34@5253.54,1125.47 5380.47,1125.47 5405,1150 5525,1150
  Top Layer w15: Q4_D.3@5523.98,1042.21 Q4_D.2@5523.98,1067.8 Q4_D.1@5523.98,1093.39 ; Q4_D.1@5525,1094.41 5525,1150 v1(5595,1150)
  Bottom Layer w30: R21_D.1@5514.53,1025 R22_D.1@5514.53,1100 5564.53,1150 v1(5595,1150)
PSE_S6_E: Q4_E.1 Q4_E.2 Q4_E.3 R21_E.1 R22_E.1 U4_E.34 | length 634.6
  Top Layer w7: U4_E.34@6703.54,1125.47 6830.47,1125.47 6855,1150 6975,1150
  Top Layer w15: Q4_E.3@6973.98,1042.21 Q4_E.2@6973.98,1067.8 Q4_E.1@6973.98,1093.39 ; Q4_E.1@6975,1094.41 6975,1150 v1(7045,1150)
  Bottom Layer w30: R21_E.1@6964.53,1025 R22_E.1@6964.53,1100 7014.53,1150 v1(7045,1150)
PSE_S6_F: Q4_F.1 Q4_F.2 Q4_F.3 R21_F.1 R22_F.1 U4_F.34 | length 634.6
  Top Layer w7: U4_F.34@8153.54,1125.47 8280.47,1125.47 8305,1150 8425,1150
  Top Layer w15: Q4_F.3@8423.98,1042.21 Q4_F.2@8423.98,1067.8 Q4_F.1@8423.98,1093.39 ; Q4_F.1@8425,1094.41 8425,1150 v1(8495,1150)
  Bottom Layer w30: R21_F.1@8414.53,1025 R22_F.1@8414.53,1100 8464.53,1150 v1(8495,1150)
PSE_S7_A: Q7_A.1 Q7_A.2 Q7_A.3 R27_A.1 R28_A.1 U4_A.37 | length 710.3
  Top Layer w7: U4_A.37@903.54,1184.53 969.53,1184.53 990,1205 1015,1205 1040,1230 1080,1230 1135,1285 1135,1325 1145,1335 1173.98,1335
  Top Layer w15: Q7_A.3@1173.98,1232.21 Q7_A.2@1173.98,1257.8 Q7_A.1@1173.98,1283.39 1173.98,1335 v1(1245,1335)
  Bottom Layer w30: R27_A.1@1164.53,1200 R28_A.1@1164.53,1275 1224.53,1335 v1(1245,1335)
PSE_S7_B: Q7_B.1 Q7_B.2 Q7_B.3 R27_B.1 R28_B.1 U4_B.37 | length 710.3
  Top Layer w7: U4_B.37@2353.54,1184.53 2419.53,1184.53 2440,1205 2465,1205 2490,1230 2530,1230 2585,1285 2585,1325 2595,1335 2623.98,1335
  Top Layer w15: Q7_B.3@2623.98,1232.21 Q7_B.2@2623.98,1257.8 Q7_B.1@2623.98,1283.39 2623.98,1335 v1(2695,1335)
  Bottom Layer w30: R27_B.1@2614.53,1200 R28_B.1@2614.53,1275 2674.53,1335 v1(2695,1335)
PSE_S7_C: Q7_C.1 Q7_C.2 Q7_C.3 R27_C.1 R28_C.1 U4_C.37 | length 710.3
  Top Layer w7: U4_C.37@3803.54,1184.53 3869.53,1184.53 3890,1205 3915,1205 3940,1230 3980,1230 4035,1285 4035,1325 4045,1335 4073.98,1335
  Top Layer w15: Q7_C.3@4073.98,1232.21 Q7_C.2@4073.98,1257.8 Q7_C.1@4073.98,1283.39 4073.98,1335 v1(4145,1335)
  Bottom Layer w30: R27_C.1@4064.53,1200 R28_C.1@4064.53,1275 4124.53,1335 v1(4145,1335)
PSE_S7_D: Q7_D.1 Q7_D.2 Q7_D.3 R27_D.1 R28_D.1 U4_D.37 | length 710.3
  Top Layer w7: U4_D.37@5253.54,1184.53 5319.53,1184.53 5340,1205 5365,1205 5390,1230 5430,1230 5485,1285 5485,1325 5495,1335 5523.98,1335
  Top Layer w15: Q7_D.3@5523.98,1232.21 Q7_D.2@5523.98,1257.8 Q7_D.1@5523.98,1283.39 5523.98,1335 v1(5595,1335)
  Bottom Layer w30: R27_D.1@5514.53,1200 R28_D.1@5514.53,1275 5574.53,1335 v1(5595,1335)
PSE_S7_E: Q7_E.1 Q7_E.2 Q7_E.3 R27_E.1 R28_E.1 U4_E.37 | length 710.3
  Top Layer w7: U4_E.37@6703.54,1184.53 6769.53,1184.53 6790,1205 6815,1205 6840,1230 6880,1230 6935,1285 6935,1325 6945,1335 6973.98,1335
  Top Layer w15: Q7_E.3@6973.98,1232.21 Q7_E.2@6973.98,1257.8 Q7_E.1@6973.98,1283.39 6973.98,1335 v1(7045,1335)
  Bottom Layer w30: R27_E.1@6964.53,1200 R28_E.1@6964.53,1275 7024.53,1335 v1(7045,1335)
PSE_S7_F: Q7_F.1 Q7_F.2 Q7_F.3 R27_F.1 R28_F.1 U4_F.37 | length 710.3
  Top Layer w7: U4_F.37@8153.54,1184.53 8219.53,1184.53 8240,1205 8265,1205 8290,1230 8330,1230 8385,1285 8385,1325 8395,1335 8423.98,1335
  Top Layer w15: Q7_F.3@8423.98,1232.21 Q7_F.2@8423.98,1257.8 Q7_F.1@8423.98,1283.39 8423.98,1335 v1(8495,1335)
  Bottom Layer w30: R27_F.1@8414.53,1200 R28_F.1@8414.53,1275 8474.53,1335 v1(8495,1335)
PSE_S8_A: Q8_A.1 Q8_A.2 Q8_A.3 R29_A.1 R30_A.1 U4_A.41 | length 954.6
  Top Layer w7: U4_A.41@903.54,1263.27 928.27,1263.27 935,1270 935,1340 940,1345 v1(970,1345)
  Top Layer w15: Q8_A.3@1173.98,1422.21 Q8_A.2@1173.98,1447.8 Q8_A.1@1173.98,1473.39 1173.98,1513.98 1185,1525 v1(1245,1525)
  Signal Layer 2 w10: v1(970,1345) 970,1495 1000,1525 v1(1245,1525)
  Bottom Layer w30: R29_A.1@1164.53,1385 R30_A.1@1164.53,1460 1164.53,1504.53 1185,1525 v1(1245,1525)
PSE_S8_B: Q8_B.1 Q8_B.2 Q8_B.3 R29_B.1 R30_B.1 U4_B.41 | length 954.6
  Top Layer w7: U4_B.41@2353.54,1263.27 2378.27,1263.27 2385,1270 2385,1340 2390,1345 v1(2420,1345)
  Top Layer w15: Q8_B.3@2623.98,1422.21 Q8_B.2@2623.98,1447.8 Q8_B.1@2623.98,1473.39 2623.98,1513.98 2635,1525 v1(2695,1525)
  Signal Layer 2 w10: v1(2420,1345) 2420,1495 2450,1525 v1(2695,1525)
  Bottom Layer w30: R29_B.1@2614.53,1385 R30_B.1@2614.53,1460 2614.53,1504.53 2635,1525 v1(2695,1525)
PSE_S8_C: Q8_C.1 Q8_C.2 Q8_C.3 R29_C.1 R30_C.1 U4_C.41 | length 954.6
  Top Layer w7: U4_C.41@3803.54,1263.27 3828.27,1263.27 3835,1270 3835,1340 3840,1345 v1(3870,1345)
  Top Layer w15: Q8_C.3@4073.98,1422.21 Q8_C.2@4073.98,1447.8 Q8_C.1@4073.98,1473.39 4073.98,1513.98 4085,1525 v1(4145,1525)
  Signal Layer 2 w10: v1(3870,1345) 3870,1495 3900,1525 v1(4145,1525)
  Bottom Layer w30: R29_C.1@4064.53,1385 R30_C.1@4064.53,1460 4064.53,1504.53 4085,1525 v1(4145,1525)
PSE_S8_D: Q8_D.1 Q8_D.2 Q8_D.3 R29_D.1 R30_D.1 U4_D.41 | length 954.6
  Top Layer w7: U4_D.41@5253.54,1263.27 5278.27,1263.27 5285,1270 5285,1340 5290,1345 v1(5320,1345)
  Top Layer w15: Q8_D.3@5523.98,1422.21 Q8_D.2@5523.98,1447.8 Q8_D.1@5523.98,1473.39 5523.98,1513.98 5535,1525 v1(5595,1525)
  Signal Layer 2 w10: v1(5320,1345) 5320,1495 5350,1525 v1(5595,1525)
  Bottom Layer w30: R29_D.1@5514.53,1385 R30_D.1@5514.53,1460 5514.53,1504.53 5535,1525 v1(5595,1525)
PSE_S8_E: Q8_E.1 Q8_E.2 Q8_E.3 R29_E.1 R30_E.1 U4_E.41 | length 954.6
  Top Layer w7: U4_E.41@6703.54,1263.27 6728.27,1263.27 6735,1270 6735,1340 6740,1345 v1(6770,1345)
  Top Layer w15: Q8_E.3@6973.98,1422.21 Q8_E.2@6973.98,1447.8 Q8_E.1@6973.98,1473.39 6973.98,1513.98 6985,1525 v1(7045,1525)
  Signal Layer 2 w10: v1(6770,1345) 6770,1495 6800,1525 v1(7045,1525)
  Bottom Layer w30: R29_E.1@6964.53,1385 R30_E.1@6964.53,1460 6964.53,1504.53 6985,1525 v1(7045,1525)
PSE_S8_F: Q8_F.1 Q8_F.2 Q8_F.3 R29_F.1 R30_F.1 U4_F.41 | length 954.6
  Top Layer w7: U4_F.41@8153.54,1263.27 8178.27,1263.27 8185,1270 8185,1340 8190,1345 v1(8220,1345)
  Top Layer w15: Q8_F.3@8423.98,1422.21 Q8_F.2@8423.98,1447.8 Q8_F.1@8423.98,1473.39 8423.98,1513.98 8435,1525 v1(8495,1525)
  Signal Layer 2 w10: v1(8220,1345) 8220,1495 8250,1525 v1(8495,1525)
  Bottom Layer w30: R29_F.1@8414.53,1385 R30_F.1@8414.53,1460 8414.53,1504.53 8435,1525 v1(8495,1525)
PSE_SCL_A: R12.1 TP17.1 U3.6 U4_A.53 U4_B.53 U4_C.53 U4_D.53 U4_E.53 U4_F.53 | length 11433.5
  Top Layer w7: 625,1675 625,1420 681.1,1363.9 U4_A.53@681.1,1308.54 ; v1(2050,1600) 2075,1575 2075,1420 2131.1,1363.9 U4_B.53@2131.1,1308.54 ; v1(3500,1600) 3525,1575 3525,1420 3581.1,1363.9 U4_C.53@3581.1,1308.54 ; v1(4950,1600) 4975,1575 4975,1420 5031.1,1363.9 U4_D.53@5031.1,1308.54 ; v1(6400,1600) 6425,1575 6425,1420 6481.1,1363.9 U4_E.53@6481.1,1308.54 ; v1(7850,1600) 7875,1575 7875,1420 7931.1,1363.9 U4_F.53@7931.1,1308.54
  Top Layer w10: 625,1675 700,1750 v1(2050,1750) v1(3500,1750) v1(4950,1750) v1(6400,1750) v1(7020,1750) v1(7850,1750) ; R12.1@7018.31,2050 7024.69,2056.38 U3.6@7024.69,2128.7 ; v1(7020,1995) R12.1@7020,2048.31
  Signal Layer 2 w10: v1(4950,1750) 4950,2100 5000,2150 5200,2150 5350,2300 TP17.1@5350,2500
  Bottom Layer w7: v1(2050,1600) v1(2050,1750) ; v1(3500,1600) v1(3500,1750) ; v1(4950,1600) v1(4950,1750)
  Bottom Layer w10: v1(6400,1600) v1(6400,1750) ; v1(7020,1750) v1(7020,1995) ; v1(7850,1600) v1(7850,1750)
PSE_SDA_A: R11.1 TP16.1 U3.7 U4_A.54 U4_A.55 U4_B.54 U4_B.55 U4_C.54 U4_C.55 U4_D.54 U4_D.55 U4_E.54 U4_E.55 U4_F.54 U4_F.55 | length 11587.5
  Top Layer w7: 600,1700 600,1385 641.73,1343.27 U4_A.55@641.73,1308.54 U4_A.54@661.42,1308.54 ; v1(2000,1600) 2050,1550 2050,1385 2091.73,1343.27 U4_B.55@2091.73,1308.54 U4_B.54@2111.42,1308.54 ; v1(3450,1600) 3500,1550 3500,1385 3541.73,1343.27 U4_C.55@3541.73,1308.54 U4_C.54@3561.42,1308.54 ; v1(4900,1600) 4950,1550 4950,1385 4991.73,1343.27 U4_D.55@4991.73,1308.54 U4_D.54@5011.42,1308.54 ; v1(6350,1600) 6400,1550 6400,1385 6441.73,1343.27 U4_E.55@6441.73,1308.54 U4_E.54@6461.42,1308.54 ; v1(7800,1600) 7850,1550 7850,1385 7891.73,1343.27 U4_F.55@7891.73,1308.54 U4_F.54@7911.42,1308.54
  Top Layer w10: 600,1700 700,1800 v1(2000,1800) v1(3450,1800) v1(4900,1800) v1(6350,1800) v1(7080,1800) v1(7800,1800) ; U3.7@7074.69,2128.7 7074.69,2056.38 R11.1@7081.06,2050 ; v1(7080,1995) R11.1@7080,2048.94
  Signal Layer 2 w10: v1(4900,1800) 4900,2150 4950,2200 5050,2200 5100,2250 5100,2500.06 TP16.1@5100.12,2500.18
  Bottom Layer w7: v1(3450,1600) v1(3450,1800) ; v1(4900,1600) v1(4900,1800) ; v1(6350,1600) v1(6350,1800) ; v1(7800,1600) v1(7800,1800)
  Bottom Layer w10: v1(2000,1600) v1(2000,1800) ; v1(7080,1800) v1(7080,1995)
